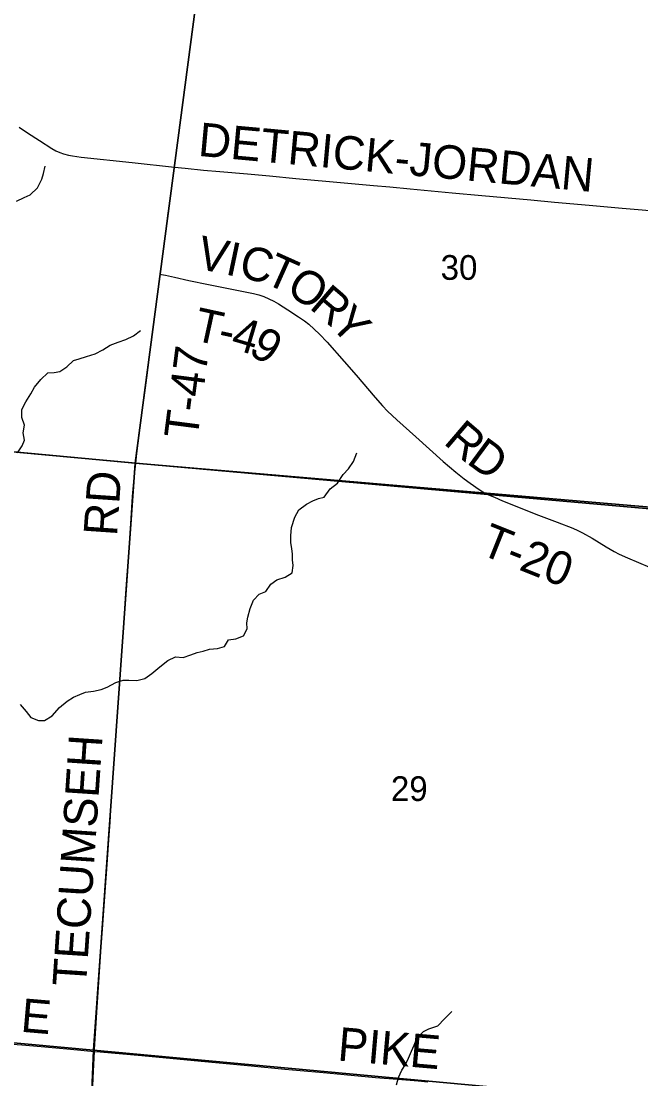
# Model space of a CAD drawing. Extents: x 0 to 680, y 0 to 440.
# Drawn here: x 255.45 to 271.86, y 322.85 to 350.9 of the extents above; entities that cross this region are included whole.
import ezdxf

# ---------------------------------------------------------------- set-up
doc = ezdxf.new("R2010")
doc.units = 0
for name, color, linetype in [('GM_X_County_Road', 7, 'Continuous'), ('GM_X_County_Road_Text', 7, 'Continuous'), ('GM_X_Minor_River', 7, 'Continuous'), ('GM_X_Section', 7, 'Continuous'), ('GM_X_Section_Text', 7, 'Continuous'), ('GM_X_Township', 7, 'Continuous'), ('GM_X_Township_Road', 7, 'Continuous'), ('GM_X_Township_Road_Text', 7, 'Continuous')]:
    doc.layers.add(name, color=color, linetype=linetype)

msp = doc.modelspace()

# ---------------------------------------------------------------- linework, layer by layer
at = {"layer": 'GM_X_County_Road'}
for points in [[(255.393, 348.086), (255.62, 347.937), (255.933, 347.729), (256.264, 347.516), (256.368, 347.458), (256.47, 347.411), (256.57, 347.374), (256.704, 347.342), (256.811, 347.321), (257.039, 347.291), (258.393, 347.146), (259.507, 347.026)], [(259.507, 347.026), (259.795, 346.995), (260.279, 346.949), (260.715, 346.907), (261.442, 346.846), (262.023, 346.796), (262.721, 346.727), (263.621, 346.648), (264.783, 346.539), (265.219, 346.502), (265.751, 346.453), (266.864, 346.347), (267.654, 346.274), (268.947, 346.158), (269.576, 346.1), (270.497, 346.019), (271.368, 345.941), (271.902, 345.897), (272.773, 345.816), (273.838, 345.72), (274.466, 345.661), (274.814, 345.63)], [(250.11, 324.391), (250.118, 324.383), (250.151, 324.349), (250.188, 324.319), (250.226, 324.291), (250.267, 324.266), (250.309, 324.244), (250.352, 324.225), (250.397, 324.209), (250.471, 324.192), (250.554, 324.177), (250.713, 324.157), (251.217, 324.111), (252.037, 324.031), (252.763, 323.965), (253.392, 323.91), (254.216, 323.839), (255.469, 323.748), (255.982, 323.706), (256.758, 323.637), (257.39, 323.578)], [(257.39, 323.578), (257.54, 323.564), (258.643, 323.465), (260.028, 323.332), (261.545, 323.191), (262.43, 323.11), (263.45, 323.016), (264.009, 322.965), (264.836, 322.889), (265.531, 322.829), (265.964, 322.793), (266.226, 322.77)]]:
    msp.add_lwpolyline(points, dxfattribs=at)
at = {"layer": 'GM_X_Minor_River'}
for points in [[(255.327, 346.123), (255.53, 346.222), (255.686, 346.291), (255.878, 346.473), (255.994, 346.704), (256.044, 346.858), (256.088, 347.048)], [(255.35, 339.45), (255.478, 339.633), (255.533, 339.787), (255.5, 339.983), (255.538, 340.179), (255.463, 340.382), (255.466, 340.602), (255.576, 340.803), (255.709, 341.01), (255.806, 341.187), (255.97, 341.394), (256.156, 341.57), (256.323, 341.58), (256.472, 341.602), (256.658, 341.73), (256.838, 341.895), (256.987, 341.941), (257.184, 342.004), (257.405, 342.073), (257.609, 342.177), (257.806, 342.306), (258.015, 342.387), (258.224, 342.456), (258.428, 342.554), (258.614, 342.689)], [(255.421, 332.774), (255.585, 332.588), (255.708, 332.432), (255.909, 332.352), (256.064, 332.35), (256.273, 332.472), (256.466, 332.696), (256.671, 332.866), (256.833, 332.966), (257, 333.041), (257.155, 333.099), (257.364, 333.132), (257.567, 333.177), (257.728, 333.235), (257.955, 333.363), (258.152, 333.42), (258.301, 333.424), (258.509, 333.416), (258.724, 333.467), (258.91, 333.596), (259.12, 333.771), (259.336, 333.942), (259.54, 334.04), (259.736, 334.026), (259.945, 334.089), (260.112, 334.153), (260.267, 334.186), (260.44, 334.244), (260.648, 334.265), (260.839, 334.316), (260.937, 334.494), (261.133, 334.521), (261.336, 334.596), (261.434, 334.785), (261.43, 334.94), (261.45, 335.095), (261.518, 335.32), (261.604, 335.539), (261.755, 335.704), (261.934, 335.773), (262.067, 335.968), (262.223, 336.079), (262.438, 336.148), (262.63, 336.271), (262.65, 336.461), (262.64, 336.61), (262.636, 336.759), (262.62, 336.913), (262.592, 337.062), (262.589, 337.247), (262.609, 337.473), (262.696, 337.739), (262.806, 337.94), (263.004, 338.087), (263.177, 338.174), (263.327, 338.238), (263.476, 338.278), (263.633, 338.496), (263.825, 338.642), (263.983, 338.873), (264.121, 339.026), (264.249, 339.22), (264.341, 339.451)], [(265.395, 322.69), (265.445, 322.885), (265.531, 323.075), (265.628, 323.234), (265.708, 323.394), (265.793, 323.583), (265.861, 323.743), (265.934, 323.921), (266.103, 324.103), (266.252, 324.173), (266.485, 324.259), (266.66, 324.442), (266.853, 324.636)]]:
    msp.add_lwpolyline(points, dxfattribs=at)
at = {"layer": 'GM_X_Section'}
for points in [[(245.115, 356.243), (260.527, 354.766), (258.466, 339.173), (243.775, 340.544)], [(260.527, 354.766), (275.758, 353.416), (274.289, 337.825), (258.466, 339.173)], [(243.775, 340.544), (258.466, 339.173), (257.365, 323.612), (242.354, 324.989)], [(258.466, 339.173), (274.289, 337.825), (272.932, 322.173), (257.365, 323.612)], [(242.354, 324.989), (257.365, 323.612), (256.695, 307.161), (240.712, 308.891)], [(257.365, 323.612), (272.932, 322.173), (271.613, 305.928), (256.695, 307.161)]]:
    msp.add_lwpolyline(points, close=True, dxfattribs=at)
at = {"layer": 'GM_X_Township'}
for points in [[(243.787, 340.531), (258.485, 339.173), (267.813, 338.347), (274.304, 337.773), (285.035, 336.894), (285.035, 415.359)], [(272.949, 322.12), (273.328, 326.241), (274.05, 334.886), (274.105, 335.472), (274.304, 337.773), (267.813, 338.347), (258.485, 339.173), (243.787, 340.531), (228.078, 341.882), (225.071, 342.231), (204.178, 344.406)]]:
    msp.add_lwpolyline(points, dxfattribs=at)
at = {"layer": 'GM_X_Township_Road'}
for points in [[(259.135, 344.187), (259.202, 344.702), (259.346, 345.808), (259.448, 346.577), (259.485, 346.861), (259.502, 346.993), (259.507, 347.026)], [(258.485, 339.172), (258.514, 339.429), (258.609, 340.185), (258.775, 341.434), (258.838, 341.915), (258.875, 342.203), (258.924, 342.587), (258.967, 342.924), (259.027, 343.356), (259.09, 343.837), (259.135, 344.187)], [(259.135, 344.187), (259.167, 344.181), (259.276, 344.16), (259.512, 344.104), (259.891, 344.019), (260.414, 343.909), (260.985, 343.796), (261.603, 343.67), (261.744, 343.636), (261.881, 343.592), (262.014, 343.536), (262.143, 343.47), (262.269, 343.399), (262.515, 343.245), (262.799, 343.058), (262.957, 342.947), (263.07, 342.857), (263.214, 342.728), (263.352, 342.593), (263.551, 342.38), (264.004, 341.875), (264.327, 341.513), (264.825, 340.917), (265.017, 340.698), (265.152, 340.557), (265.401, 340.325), (265.907, 339.872), (266.628, 339.222), (266.96, 338.938), (267.188, 338.756), (267.345, 338.641), (267.58, 338.479), (267.681, 338.415), (267.74, 338.383), (267.813, 338.347)], [(257.39, 323.578), (257.393, 323.633), (257.464, 324.75), (257.572, 326.352), (257.612, 326.935), (257.674, 327.808), (257.727, 328.536), (257.782, 329.309), (257.805, 329.653), (257.837, 330.137), (257.853, 330.38), (257.871, 330.671), (257.91, 331.254), (257.953, 331.885), (258.007, 332.613), (258.077, 333.583), (258.102, 333.923), (258.142, 334.505), (258.19, 335.185), (258.225, 335.719), (258.257, 336.204), (258.297, 336.787), (258.333, 337.321), (258.36, 337.709), (258.401, 338.291), (258.442, 338.776), (258.485, 339.172)], [(267.813, 338.347), (267.874, 338.319), (267.984, 338.271), (268.203, 338.178), (269.152, 337.799), (269.651, 337.607), (270.059, 337.45), (270.192, 337.392), (270.321, 337.327), (270.575, 337.186), (270.949, 336.958), (271.158, 336.834), (271.288, 336.766), (271.509, 336.664), (272.093, 336.421)], [(257.083, 316.462), (257.102, 316.827), (257.126, 317.41), (257.163, 318.188), (257.189, 318.82), (257.208, 319.257), (257.23, 319.792), (257.265, 320.716), (257.302, 321.542), (257.325, 322.078), (257.366, 323.05), (257.39, 323.578)]]:
    msp.add_lwpolyline(points, dxfattribs=at)

# ---------------------------------------------------------------- texts
at = {"layer": 'GM_X_County_Road_Text'}
for s, height, rotation, p in [('DETRICK-JORDAN', 0.88938, 354.7624, (260.118, 347.326)), ('E', 0.889, 355.0853, (255.418, 324.101)), ('PIKE', 0.8894, 355.0831, (263.813, 323.337))]:
    msp.add_text(s, height=height, rotation=rotation, dxfattribs=at).set_placement(p)
at = {"layer": 'GM_X_Section_Text'}
for s, p in [('30', (266.561, 344.037)), ('29', (265.243, 330.217))]:
    msp.add_text(s, height=0.6552, rotation=0, dxfattribs=at).set_placement(p)
at = {"layer": 'GM_X_Township_Road_Text'}
for s, height, rotation, p in [('V', 0.889, 348.1978, (260.065, 344.346)), ('I', 0.889, 348.168, (260.83, 344.186)), ('C', 0.889, 347.2011, (261.184, 344.112)), ('T', 0.889, 335.8965, (261.852, 343.965)), ('O', 0.889, 326.5403, (262.426, 343.712)), ('R', 0.889, 319.5778, (263.056, 343.297)), ('T', 0.889, 347.6781, (259.977, 342.443)), ('Y', 0.889, 313.1064, (263.593, 342.842)), ('4', 0.889, 343.5435, (260.967, 342.227)), ('9', 0.889, 327.8573, (261.434, 342.098)), ('-', 0.889, 347.6016, (260.626, 342.301)), ('T-47', 0.8894, 82.6601, (260.115, 339.789)), ('R', 0.889, 319.5088, (266.61, 339.707)), ('D', 0.889, 323.5953, (267.219, 339.191)), ('RD', 0.8894, 86.0508, (257.987, 337.227)), ('T-20', 0.8894, 338.2081, (267.563, 336.777)), ('TECUMSEH', 0.8894, 86.211, (257.165, 325.279))]:
    msp.add_text(s, height=height, rotation=rotation, dxfattribs=at).set_placement(p)

doc.saveas('drawing.dxf')
